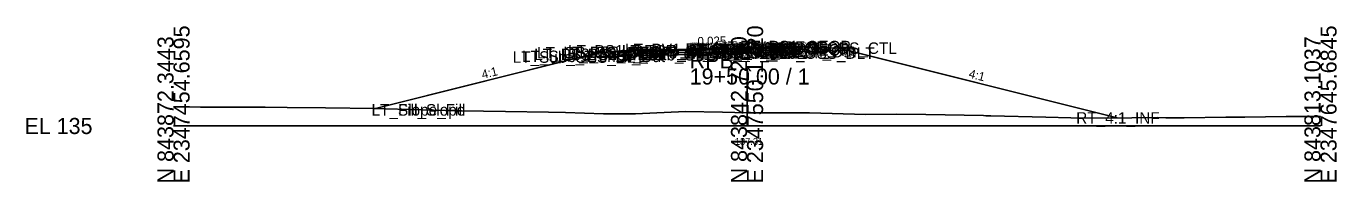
# Model space of a CAD drawing. Extents: x -76 to 2347760, y -10 to 844216.
# Drawn here: x -25.7 to 202.8, y 4490.3 to 4517.3 of the extents above; entities that cross this region are included whole.
import ezdxf

# ---------------------------------------------------------------- set-up
doc = ezdxf.new("R2010")
doc.units = 0
for name, color, linetype in [('Default', 7, 'Continuous'), ('Exist Cross Section Cell', 7, 'Continuous'), ('Exist XS Center Line Elevation Label', 7, 'Continuous'), ('Exist XS Ground Line', 7, 'Continuous'), ('Prop CMT Pvmt Course 1', 7, 'Continuous'), ('Prop CMT Pvmt Course 2', 7, 'Continuous'), ('Prop CMT Pvmt Course 3', 7, 'Continuous'), ('Prop CMT Pvmt Surface', 7, 'Continuous'), ('Prop CMT Pvmt Surface Shoulder', 7, 'Continuous'), ('Prop CMT Shld Paved Course 1', 7, 'Continuous'), ('Prop CMT Shld Paved Course 2', 7, 'Continuous'), ('Prop CMT Shld Paved Course 3', 7, 'Continuous'), ('Prop CMT Slope Grass', 7, 'Continuous'), ('Prop CMT Subgrade Earthwork', 7, 'Continuous'), ('Prop XS Earthwork Shape', 7, 'Continuous'), ('Prop XS SE Text', 7, 'Continuous'), ('Prop XS Side Slope Text', 7, 'Continuous'), ('Scratch_Level_0', 7, 'Continuous')]:
    doc.layers.add(name, color=color, linetype=linetype)

msp = doc.modelspace()

# ---------------------------------------------------------------- linework, layer by layer
at = {"layer": 'Exist Cross Section Cell'}
for p, q in [((100, 4500), (100, 4510.01)), ((0, 4500), (100, 4500)), ((100, 4500), (200, 4500))]:
    msp.add_line(p, q, dxfattribs=at)
at = {"layer": 'Exist XS Ground Line'}
msp.add_lwpolyline([(0, 4503.34), (4.67, 4503.3), (5.53, 4503.3), (7.44, 4503.29), (16, 4503.27), (19.84, 4503.19), (26.47, 4503.17), (35.02, 4503.04), (36.94, 4502.98), (41.2, 4502.88), (47.41, 4502.7), (50.2, 4502.65), (57.88, 4502.54), (65.38, 4502.43), (68.35, 4502.35), (74.96, 4502.13), (78.82, 4502.09), (80.55, 4502.1), (89.29, 4502.5), (95.73, 4502.41), (100, 4502.31), (108.73, 4502.31), (110.23, 4502.28), (110.91, 4502.27), (120.7, 4502.02), (126.08, 4502.04), (131.17, 4501.98), (141.26, 4501.8), (141.64, 4501.79), (142.49, 4501.78), (152.11, 4501.53), (156.44, 4501.4), (162.58, 4501.38), (171.61, 4501.46), (173.05, 4501.43), (176.25, 4501.43), (183.52, 4501.51), (186.79, 4501.53), (193.99, 4501.62), (200, 4501.66)], dxfattribs=at)
at = {"layer": 'Prop CMT Pvmt Course 1'}
for p, q in [((100, 4513.61), (88, 4513.31)), ((100, 4513.61), (104, 4513.71)), ((100, 4513.36), (100, 4513.61)), ((100, 4513.36), (100, 4513.61)), ((104, 4513.71), (104, 4513.46)), ((88, 4513.06), (100, 4513.36)), ((88, 4513.31), (88, 4513.06)), ((100, 4513.36), (100, 4513.48)), ((100, 4513.48), (100, 4513.48)), ((100, 4513.48), (100, 4513.36)), ((100, 4513.36), (100, 4513.48)), ((100, 4513.48), (100, 4513.48)), ((100, 4513.48), (100, 4513.36)), ((104, 4513.46), (100, 4513.36)), ((100, 4513.36), (100, 4513.36)), ((100, 4513.36), (100, 4513.36))]:
    msp.add_line(p, q, dxfattribs=at)
at = {"layer": 'Prop CMT Pvmt Course 2'}
for p, q in [((100, 4513.36), (88, 4513.06)), ((88, 4513.06), (88, 4512.73)), ((88, 4512.73), (100, 4513.03)), ((100, 4513.36), (104, 4513.46)), ((100, 4513.03), (100, 4513.36)), ((100, 4513.03), (100, 4513.36)), ((104, 4513.13), (100, 4513.03)), ((104, 4513.46), (104, 4513.13))]:
    msp.add_line(p, q, dxfattribs=at)
at = {"layer": 'Prop CMT Pvmt Course 3'}
for p, q in [((100, 4513.03), (88, 4512.73)), ((88, 4512.73), (88, 4512.39)), ((88, 4512.39), (100, 4512.69)), ((100, 4513.03), (104, 4513.13)), ((100, 4512.69), (100, 4513.03)), ((100, 4512.69), (100, 4513.03)), ((104, 4512.79), (100, 4512.69)), ((104, 4513.13), (104, 4512.79))]:
    msp.add_line(p, q, dxfattribs=at)
at = {"layer": 'Prop CMT Pvmt Surface'}
for q in [(88, 4513.31), (104, 4513.71)]:
    msp.add_line((100, 4513.61), q, dxfattribs=at)
at = {"layer": 'Prop CMT Pvmt Surface Shoulder'}
for p, q in [((104, 4513.71), (108, 4513.81)), ((88, 4513.31), (78, 4513.06))]:
    msp.add_line(p, q, dxfattribs=at)
at = {"layer": 'Prop CMT Shld Paved Course 1'}
for p, q in [((104, 4513.71), (108, 4513.81)), ((104, 4513.46), (104, 4513.71)), ((108.24, 4513.57), (104, 4513.46)), ((108, 4513.81), (108.24, 4513.57)), ((78, 4513.06), (77.74, 4512.8)), ((77.74, 4512.8), (88, 4513.06)), ((88, 4513.31), (78, 4513.06)), ((88, 4513.06), (88, 4513.31))]:
    msp.add_line(p, q, dxfattribs=at)
at = {"layer": 'Prop CMT Shld Paved Course 2'}
for p, q in [((104, 4513.46), (108.24, 4513.57)), ((108.24, 4513.57), (108.57, 4513.24)), ((77.74, 4512.8), (77.4, 4512.46)), ((77.4, 4512.46), (88, 4512.73)), ((88, 4513.06), (77.74, 4512.8)), ((88, 4512.73), (88, 4513.06)), ((104, 4513.13), (104, 4513.46)), ((108.57, 4513.24), (104, 4513.13))]:
    msp.add_line(p, q, dxfattribs=at)
at = {"layer": 'Prop CMT Shld Paved Course 3'}
for p, q in [((76.9, 4512.45), (76.56, 4512.11)), ((76.56, 4512.11), (88, 4512.39)), ((77.4, 4512.46), (76.9, 4512.45)), ((88, 4512.73), (77.4, 4512.46)), ((88, 4512.39), (88, 4512.73)), ((104, 4513.13), (108.57, 4513.24)), ((104, 4512.79), (104, 4513.13)), ((109.39, 4512.93), (104, 4512.79)), ((108.57, 4513.24), (109.07, 4513.25)), ((109.07, 4513.25), (109.39, 4512.93))]:
    msp.add_line(p, q, dxfattribs=at)
at = {"layer": 'Prop CMT Slope Grass'}
for p, q in [((108, 4513.81), (116, 4513.53)), ((116, 4513.53), (164.52, 4501.4)), ((74, 4512.74), (35.19, 4503.04)), ((78, 4513.06), (74, 4512.74))]:
    msp.add_line(p, q, dxfattribs=at)
at = {"layer": 'Prop CMT Subgrade Earthwork'}
for p, q in [((76.56, 4512.11), (70.9, 4511.97)), ((88, 4512.39), (76.56, 4512.11)), ((100, 4512.69), (88, 4512.39)), ((100, 4512.69), (104, 4512.79)), ((104, 4512.79), (117.59, 4513.13))]:
    msp.add_line(p, q, dxfattribs=at)
at = {"layer": 'Prop XS Earthwork Shape'}
msp.add_lwpolyline([(100, 4512.69), (88, 4512.39), (76.56, 4512.11), (70.9, 4511.97), (35.19, 4503.04), (36.94, 4502.98), (41.2, 4502.88), (47.41, 4502.7), (50.2, 4502.65), (57.88, 4502.54), (65.38, 4502.43), (68.35, 4502.35), (74.96, 4502.13), (78.82, 4502.09), (80.55, 4502.1), (89.29, 4502.5), (95.73, 4502.41), (100, 4502.31), (108.73, 4502.31), (110.23, 4502.28), (110.91, 4502.27), (120.7, 4502.02), (126.08, 4502.04), (131.17, 4501.98), (141.26, 4501.8), (141.64, 4501.79), (142.49, 4501.78), (152.11, 4501.53), (156.44, 4501.4), (162.58, 4501.38), (164.52, 4501.4), (117.59, 4513.13), (104, 4512.79)], close=True, dxfattribs=at)

# ---------------------------------------------------------------- texts
at = {"layer": 'Default'}
msp.add_text('-', height=0.0001, dxfattribs=at).set_placement((0, 4500))
at = {"layer": 'Exist Cross Section Cell'}
for s, p in [('E 2347454.6595', (2.8, 4490)), ('E 2347550.1720', (102.8, 4490)), ('E 2347645.6845', (202.8, 4490)), ('N 843872.3443', (0, 4490)), ('N 843842.7240', (100, 4490)), ('N 843813.1037', (200, 4490))]:
    msp.add_text(s, height=2.8, rotation=90, dxfattribs=at).set_placement(p)
for s, p in [('RPB', (90, 4510.01)), ('19+50.00 / 1', (90, 4507.21)), ('EL 135', (-26, 4498.6))]:
    msp.add_text(s, height=2.8, dxfattribs=at).set_placement(p)
at = {"layer": 'Exist XS Center Line Elevation Label'}
msp.add_text('137.31', height=1.2, dxfattribs=at).set_placement((97.89, 4496.71))
at = {"layer": 'Prop XS SE Text'}
msp.add_text('0.025', height=1.5, rotation=1.4321, dxfattribs=at).set_placement((91.38, 4513.97))
at = {"layer": 'Prop XS Side Slope Text'}
for rotation, p in [(14.0362, (53.92, 4508.18)), (345.9638, (138.57, 4508.44))]:
    msp.add_text('4:1', height=1.5, rotation=rotation, dxfattribs=at).set_placement(p)
at = {"layer": 'Scratch_Level_0'}
for s, p in [('LT_PS3_Shelf_Out', (62.89, 4511.45)), ('LT_GS_OS_CTL', (63.37, 4511.74)), ('LT_PS2_OEOP', (67.98, 4511.8)), ('LT_PS1_OEOP', (68.8, 4512.06)), ('LT_PV2_OEOT', (78.17, 4512.06)), ('LT_PV3_OEOT', (78.17, 4511.73)), ('LT_PV1_OEOT', (78.74, 4512.31)), ('RT_Sub_OEEOP', (89.17, 4511.69)), ('LT_Sub_OEEOP', (89.21, 4511.69)), ('RT_PV2_OEEOP', (89.26, 4512.36)), ('RT_PV3_OEEOP', (89.26, 4512.03)), ('LT_PV2_OEEOP', (89.31, 4512.36)), ('LT_PV3_OEEOP', (89.31, 4512.03)), ('RT_PV1_OEEOP', (89.83, 4512.48)), ('LT_PV1_OEEOP', (89.87, 4512.48)), ('RT_PV2_IEEOP', (89.91, 4512.36)), ('LT_PV2_IEEOP', (89.95, 4512.36)), ('RT_PV1_IEEOP', (90.47, 4512.48)), ('LT_PV1_IEEOP', (90.52, 4512.48)), ('RT_Sub_Trench_Out', (93.55, 4511.93)), ('PV2_PGL', (93.91, 4512.36)), ('RT_Sub_OEOT', (94.03, 4511.79)), ('RT_PV2_OEOT', (94.13, 4512.46)), ('RT_PV3_OEOT', (94.13, 4512.13)), ('PV1_PGL', (94.47, 4512.61)), ('RT_PV1_OEOT', (94.69, 4512.71)), ('RT_PS3_Shelf_Out', (95.01, 4512.25)), ('RT_PS2_OEOP', (98.43, 4512.57)), ('RT_Sub_OSS_DLT', (98.75, 4511.67)), ('RT_PS1_OEOP', (98.76, 4512.81)), ('RT_PS3_OEOP', (98.76, 4512.24)), ('RT_GS_OS_CTL', (105.32, 4512.53)), ('LT_Sub_OSS_DLT', (59.13, 4510.99)), ('LT_Sub_Trench_Out', (60.76, 4511.11)), ('LT_PS3_OEOP', (67.64, 4511.46)), ('LT_Sub_OEOT', (78.08, 4511.39)), ('LT_Fill_Slope', (34.52, 4501.8)), ('LT_Slope_Fill', (34.52, 4501.8)), ('RT_4:1_INF', (157.4, 4500.4))]:
    msp.add_text(s, height=2, dxfattribs=at).set_placement(p)

doc.saveas('drawing.dxf')
